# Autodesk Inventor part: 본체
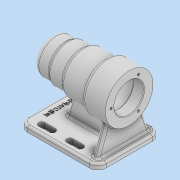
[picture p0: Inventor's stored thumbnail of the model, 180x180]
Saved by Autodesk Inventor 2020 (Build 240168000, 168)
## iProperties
Created: 2021-10
Part Number: 본체
Material: 일반
Document SubType Name: Modeling
Designer: user
Density: 1 g/cm^3
Appearance: 기본값
Author: user
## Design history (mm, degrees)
sketch "스케치1"
  geometry: L1 (-130, 0)-(0, 0); L2 (0, 21)-(-15, 21); L3 (-15, 21)-(-15, 24); L4 (-15, 24)-(-69, 24); L5 (-69, 24)-(-69, 21); L6 (-69, 21)-(-81, 21); L7 (-81, 21)-(-81, 17.5); L8 (-81, 17.5)-(-99, 17.5); L9 (-99, 17.5)-(-99, 16); L10 (-99, 16)-(-103, 16); L11 (-103, 16)-(-103, 10.5); L12 (-103, 10.5)-(-106, 10.5); L13 (-106, 10.5)-(-106, 0); L14 (0, 34)-(-32, 34); L15 (0, 34)-(0, 21); L16 (-32, 30)-(-66, 30); L17 (-32, 34)-(-32, 30); L18 (-66, 30)-(-66, 27); L19 (-66, 27)-(-88, 27); L20 (-88, 27)-(-88, 25); L21 (-88, 25)-(-112, 25); L22 (-112, 25)-(-112, 0); L23 (-112, 0)-(-106, 0); 2 further points
  constraints: 46 end point, 8 horizontal, 8 vertical, 6 perpendicular, 2 vertical alignment, 1 coincident, 1 point on line
  dimensions: "d0" = 130 distance of L1.start L1.end; "d1" = 15 distance of L2.start L2.end; "d2" = 3 distance of L2.end L3.end; "d3" = 54 distance of L3.end L4.end; "d4" = 3 distance of L4.end L5.end; "d5" = 12 distance of L5.end L6.end; "d6" = 3.5 distance of L6.end L7.end; "d7" = 18 distance of L7.end L8.end; "d8" = 1.5 distance of L8.end L9.end; "d9" = 4 distance of L9.end L10.end; "d10" = 5.5 distance of L10.end L11.end; "d11" = 3 distance of L11.end L12.end; "d12" = 10.5 distance of L12.end L13.end; "d13" = 21 distance of point (0, 0) L2.start; "d14" = 32 distance of L14.start L14.end; "d15" = 34 distance of point (0, 0) L14.start; "d16" = 34 distance of L16.start L16.end; "d17" = 4 distance of L14.end L16.start; "d18" = 3 distance of L16.end L18.end; "d19" = 22 distance of L18.end L19.end; "d20" = 2 distance of L19.end L20.end; "d21" = 24 distance of L20.end L21.end
revolve "회전1" sketch "스케치1" stored, may be unused: angle "d22" = 90 deg
node "작업 평면1"
sketch "스케치2"
  geometry: L1 (112, 45)-(0, 45); L2 (0, 45)-(0, -45); L3 (0, -45)-(112, -45); L4 (112, -45)-(112, 45); 2 further points
  constraints: 8 end point, 2 coincident, 2 parallel, 1 horizontal, 1 midpoint, 1 perpendicular
  dimensions: "d24" = 90 distance of L1.end L2.end; "d25" = 112 distance of L1.start L1.end
extrude "돌출1" join sketch "스케치2" distance "d26" = 8; taper "d27" = 0 deg
sketch "스케치3"
  geometry: L1 (-85, 4)-(-8, 4); L2 (-8, 4)-(-8, -4); L3 (-8, -4)-(-85, -4); L4 (-85, -4)-(-85, 4); L5 (0, -45)-(0, 45) reference; L6 (0, 45)-(-112, 45) reference; 3 further points
  constraints: 8 end point, 2 midpoint, 2 parallel, 1 horizontal, 1 horizontal alignment, 1 perpendicular
  dimensions: "d28" = 8 distance between parallel lines of L5 L2; "d31" = 77 distance of L1.start L1.end; "d32" = 8 distance between parallel lines of L3 L1
extrude "돌출2" join sketch "스케치3" stored distance "d33" = 8; taper "d34" = 0 deg
feature "면 기울기1" dims angle "d35" = 15 deg
node "작업 평면2"
sketch "스케치5"
  geometry: L1 (45, -62)-(-45, -62) reference; L2 (-37, -62)-(-23.409, -24.658); 2 further points
  constraints: 2 end point, 1 point on line, 2 other
  dimensions: "d37" = 110 deg angle of L2 L1; "d38" = 8 distance of L1.end L2.start
feature "리브1" sketch "스케치5" dims "d39" = 1, "d40" = 8, "d41" = 0, "d42" = 0, "d43" = 1, "d44" = 1
sketch "스케치6"
  geometry: L1 (23.409, -24.658)-(37, -62); L2 (-45, -62)-(45, -62) reference; A1 r 34 centre (0, 0) between (4, -33.764) and (-4, -33.764) reference; 1 further point
  constraints: 2 end point, 1 point on circle, 1 point on line
  dimensions: "d45" = 110 deg angle of L2 L1; "d46" = 8 distance of L2.end L1.end
feature "리브2" sketch "스케치6" dims "d47" = 1, "d48" = 8, "d49" = 0, "d50" = 0, "d51" = 1, "d52" = 1
sketch "스케치7"
  geometry: L1 (-92, 33)-(-77, 33); L2 (-92, 28.5)-(-77, 28.5); L3 (-77, 37.5)-(-92, 37.5); L4 (-112, -45)-(-112, 45) reference; L5 (-52, 33)-(-37, 33); L6 (-52, 28.5)-(-37, 28.5); L7 (-37, 37.5)-(-52, 37.5); L8 (-92, -37.5)-(-77, -37.5); L9 (-92, -33)-(-77, -33); L10 (-77, -28.5)-(-92, -28.5); L11 (-52, -37.5)-(-37, -37.5); L12 (-52, -33)-(-37, -33); L13 (-37, -28.5)-(-52, -28.5); A1 r 4.5 centre (-92, 33) between (-92, 37.5) and (-92, 28.5); A2 r 4.5 centre (-77, 33) between (-77, 28.5) and (-77, 37.5); A3 r 4.5 centre (-52, 33) between (-52, 37.5) and (-52, 28.5); A4 r 4.5 centre (-37, 33) between (-37, 28.5) and (-37, 37.5); A5 r 4.5 centre (-92, -33) between (-92, -28.5) and (-92, -37.5); A6 r 4.5 centre (-77, -33) between (-77, -37.5) and (-77, -28.5); A7 r 4.5 centre (-52, -33) between (-52, -28.5) and (-52, -37.5); A8 r 4.5 centre (-37, -33) between (-37, -37.5) and (-37, -28.5); 5 further points
  constraints: 32 end point, 16 point on circle, 16 tangent, 8 centre point, 4 horizontal, 4 midpoint, 4 parallel, 2 horizontal alignment, 2 vertical alignment
  dimensions: "d54" = 9 distance between parallel lines of L2 L3; "d55" = 15 distance of L1.start L1.end; "d56" = 20 distance from line of L4 L1.start; "d57" = 33 vertical distance of point (0, 0) point (-84.5, 33); "d58" = 9 diameter of A4; "d59" = 15 distance of L5.start L5.end; "d60" = 9 diameter of A6; "d61" = 15 distance of L9.start L9.end; "d62" = 9 diameter of A8; "d63" = 15 distance of L12.start L12.end; "d64" = 33 vertical distance of point (-84.5, -33) point (0, 0); "d65" = 25 distance of L1.end L5.start
extrude "돌출3" cut sketch "스케치7" distance "d66" = 8; taper "d67" = 0 deg
sketch "스케치8" dims "d68" = 52
  geometry: C1 r 10.5 at (0, 0) reference; 5 further points
  constraints: 2 horizontal alignment, 1 coincident, 6 other
  dimensions: "d71" = 360 deg dimension on point (0, 0) point (-26, 0) (derived)
hole "구멍1" sketch "스케치8" at (-26, 0), (13, -22.517), (13, 22.517) diameter "d73" = 3.242; stored, may be unused: countersink angle "d77" = 90 deg, drill point angle "d79" = 118 deg; dims "d74" = 8, "d75" = 8, "d76" = 10, "d78" = 11
fillet "모깎기1" dims "d80" = 0.3
fillet "모깎기2" dims "d81" = 3
chamfer "모따기1" distance "d82" = 1; stored, may be unused: second distance "d83" = 2, angle "d84" = 45 deg
fillet "모깎기3" dims "d85" = 12
fillet "모깎기4" dims "d86" = 3
fillet "모깎기5" dims "d87" = 8
fillet "모깎기6" dims "d88" = 3
sketch "스케치10"
  geometry: L1 (-109, -33)-(-109, 33) reference; L2 (-112, 33)-(-112, -33) reference; 3 further points
  constraints: 1 horizontal alignment, 1 midpoint, 1 other
  dimensions: "d89" = 12 distance from line of point (-100, 0) L2
feature "엠보싱1" sketch "스케치10" dims "d0" = 130, "d1" = 15, "d2" = 3, "d3" = 54, "d4" = 3, "d5" = 12, "d6" = 3.5, "d7" = 18, "d8" = 1.5, "d9" = 4, "d10" = 5.5, "d11" = 3, "d12" = 10.5, "d13" = 21, "d14" = 32, "d15" = 34, "d16" = 34, "d17" = 4, "d18" = 3, "d19" = 22, "d20" = 2, "d21" = 24, "d90" = 0.5, "d91" = 0
fillet "모깎기7" dims "d92" = 3
node "솔리드1"
feature "A9D066F2-1C7D-4E18-AEED-F7BC21143FA4" dims "d73" = 3.242, "d74" = 8, "d75" = 8, "d76" = 10, "d77" = 90 deg, "d78" = 11, "d79" = 118 deg
other parameters: "d36" = -12
